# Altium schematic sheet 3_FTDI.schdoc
size 307 x 218 mm; Symbol: Sheet-Symbol_A4; Device: Sheet-Symbol_A4; @Project Name: Hexapod; @Page Count: 5; @Update Date: 2024-12-17; @Create Date: 2024-10-16; @Schematic Name: Schematic1; @Page No: 3; @Page Name: FTDI; Company: EasyEDA.com; Version: V1.0; Page Size: A4; @Create Time: 17:26:46; @Update Time: 18:06:18; Title Block Position: 3; Width: 1170; Height: 825; Region Start: 1; X Region Count: 6; Y Region Count: 4; Blade Width: 10; @Board Name: Hexapod
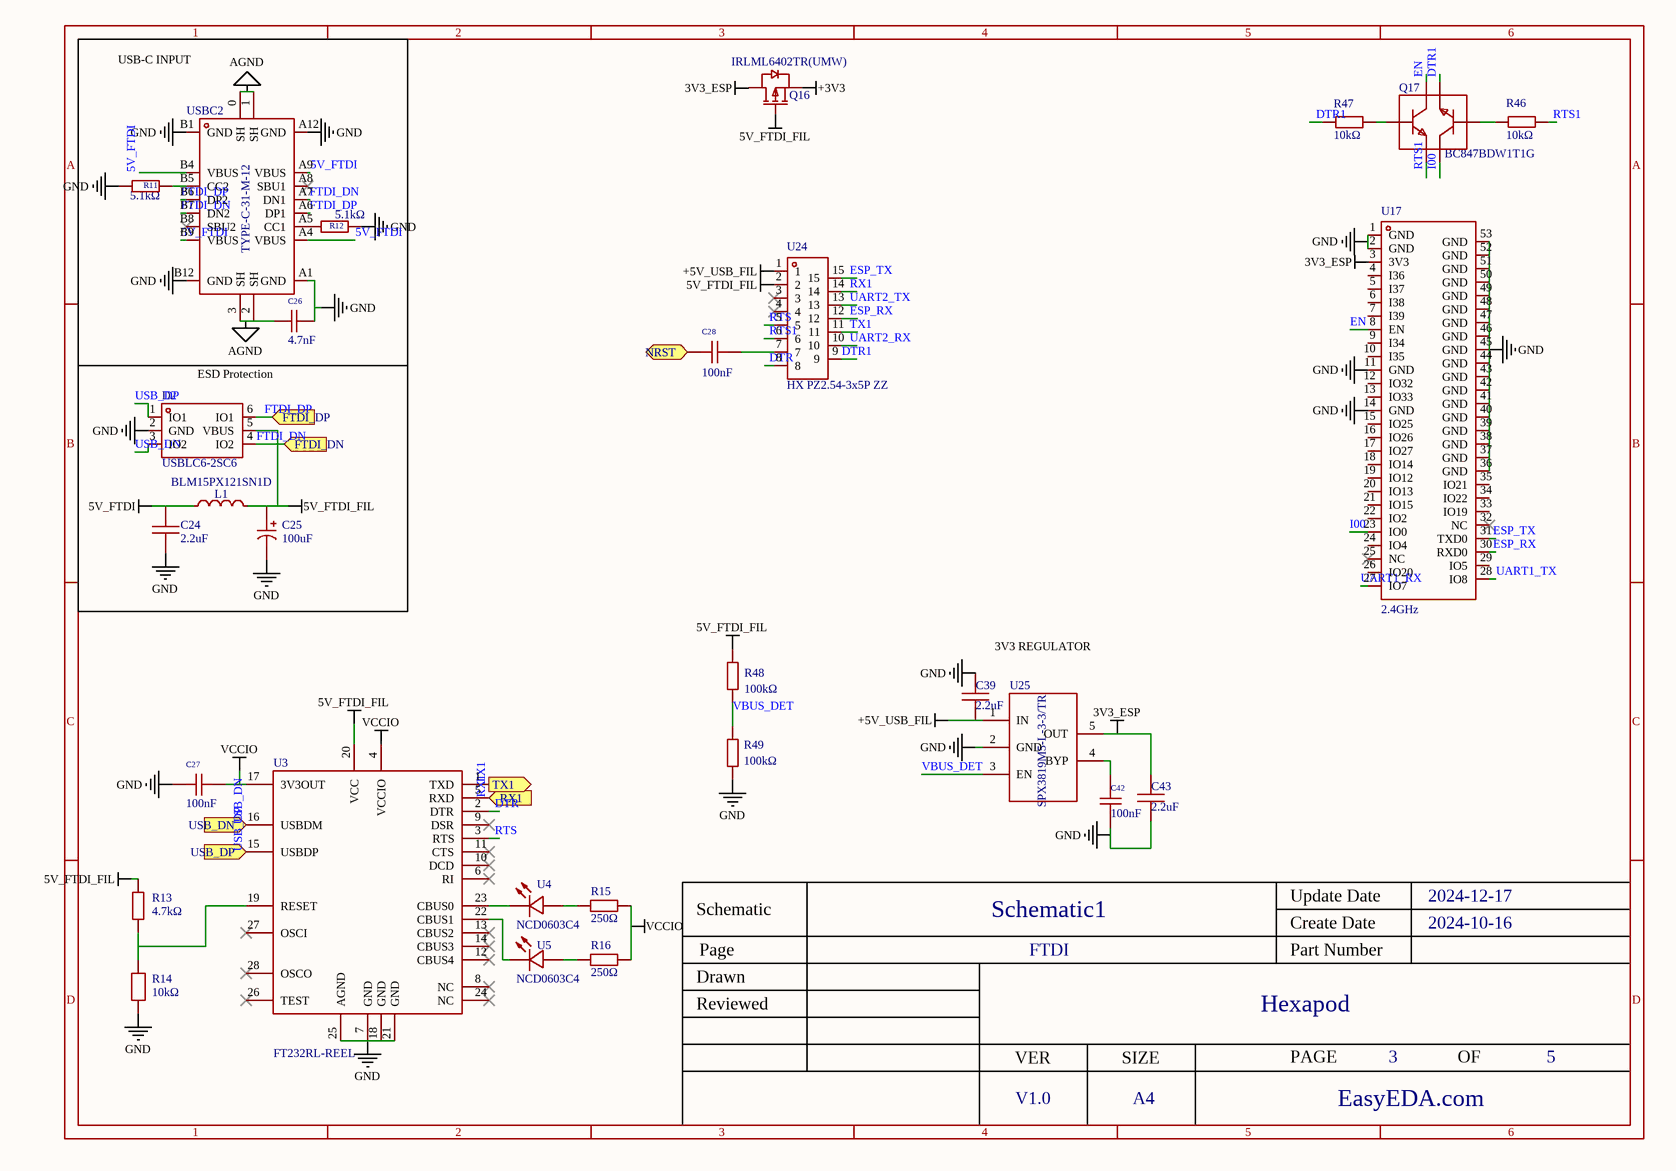
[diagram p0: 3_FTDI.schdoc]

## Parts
C24  2.2uF  [C0402]
C25  100uF  [CAP-SMD_BD5.0-L5.3-W5.3-LS6.3-FD]
C26  4.7nF  [C0402]
C27  100nF  [C0402]
C28  100nF  [C0603]
C39  2.2uF  [C0402]
C42  100nF  [C0402]
C43  2.2uF  [C0402]
D2  USBLC6-2SC6  [SOT-23-6_L2.9-W1.6-P0.95-LS2.8-BL]
L1  BLM15PX121SN1D  [L0402]
Q16  IRLML6402TR(UMW)  [SOT-23_L2.9-W1.3-P1.90-LS2.4-BR]
Q17  BC847BDW1T1G  [SOT-363_L2.0-W1.3-P0.65-LS2.1-TL]
R11  5.1kΩ  [R0402]
R12  5.1kΩ  [R0402]
R13  4.7kΩ  [R0603]
R14  10kΩ  [R0603]
R15  250Ω  [R0603]
R16  250Ω  [R0603]
R46  10kΩ  [R0402]
R47  10kΩ  [R0402]
R48  100kΩ  [R0402]
R49  100kΩ  [R0402]
U3  FT232RL-REEL  [SSOP-28_L10.2-W5.3-P0.65-LS7.8-BL]
U4  NCD0603C4  [LED0603-RD]
U5  NCD0603C4  [LED0603-RD]
U17  2.4GHz  [BULETM-SMD_ESP32-PICO-MINI-02-N8R2]
U24  HX PZ2.54-3x5P ZZ  [HDR-TH_15P-P2.54-V-M-R3-C5-S7.5]
U25  SPX3819M5-L-3-3/TR  [SOT-23-5_L3.0-W1.7-P0.95-LS2.8-BL]
USBC2  TYPE-C-31-M-12  [USB-C_SMD-TYPE-C-31-M-12]

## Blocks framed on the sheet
USB-C INPUT: C26 R11 R12 USBC2
ESD Protection: C24 C25 D2 L1

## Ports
FTDI_DN (in), FTDI_DP (in), NRST (bidir), RX1 (in), TX1 (out), USB_DN (in), USB_DP (in)

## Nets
3V3_ESP: C43.2 Q16.3(C) U17.3(3V3) U25.5(OUT)
5V_FTDI: C24.2 L1.1 USBC2.A4(VBUS) USBC2.A9(VBUS) USBC2.B4(VBUS) USBC2.B9(VBUS)
5V_FTDI_FIL: C25.1 D2.5(VBUS) L1.2 Q16.1(B) R13.2 R48.2 U3.20(VCC) U24.2
+3V3: Q16.2(E)
+5V_USB_FIL: C39.1 U24.1 U25.1(IN)
AGND: C26.1 USBC2.0(SH) USBC2.1(SH) USBC2.2(SH) USBC2.3(SH)
GND: C24.1 C25.2 C26.2 C27.1 C39.2 C42.1 C43.1 D2.2(GND) R11.1 R12.2 R14.2 R49.1 U3.7(GND) U3.18(GND) U3.21(GND) U3.25(AGND) U17.1(GND) U17.2(GND) U17.11(GND) U17.14(GND) U17.36(GND) U17.37(GND) U17.38(GND) U17.39(GND) U17.40(GND) U17.41(GND) U17.42(GND) U17.43(GND) U17.44(GND) U17.45(GND) U17.46(GND) U17.47(GND) U17.48(GND) U17.49(GND) U17.50(GND) U17.51(GND) U17.52(GND) U17.53(GND) U25.2(GND) USBC2.A1(GND) USBC2.A12(GND) USBC2.B1(GND) USBC2.B12(GND)
VCCIO: C27.2 R15.2 R16.2 U3.4(VCCIO) U3.17(3V3OUT)
DTR: U3.2(DTR) U24.8
DTR1: Q17.1(E) R47.1 U24.9
EN: Q17.3(C) U17.8(EN)
ESP_RX: U17.30(RXD0) U24.12
ESP_TX: U17.31(TXD0) U24.15
FTDI_DN: D2.4(IO2) USBC2.A7(DN1) USBC2.B7(DN2) ; port FTDI_DN
FTDI_DP: D2.6(IO1) USBC2.A6(DP1) USBC2.B6(DP2) ; port FTDI_DP
I00: Q17.6(C) U17.23(IO0)
NRST: C28.2 ; port NRST
RTS: U3.3(RTS) U24.5
RTS1: Q17.4(E) R46.2 U24.6
RX1: U3.5(RXD) U24.14 ; port RX1
TX1: U3.1(TXD) U24.11 ; port TX1
UART1_RX: U17.27(IO7)
UART1_TX: U17.28(IO8)
UART2_RX: U24.10
UART2_TX: U24.13
USB_DN: D2.3(IO2) U3.16(USBDM) ; port USB_DN
USB_DP: D2.1(IO1) U3.15(USBDP) ; port USB_DP
VBUS_DET: R48.1 R49.2 U25.3(EN)
NetC28_1: C28.1 U24.7
NetC42_2: C42.2 U25.4(BYP)
NetQ17_2: Q17.2(B) R46.1
NetQ17_5: Q17.5(B) R47.2
NetR11_2: R11.2 USBC2.B5(CC2)
NetR12_1: R12.1 USBC2.A5(CC1)
NetR13_1: R13.1 R14.1 U3.19(RESET)
NetR15_1: R15.1 U4.2(+)
NetR16_1: R16.1 U5.2(+)
NetU3_22: U3.22(CBUS1) U5.1(-)
NetU3_23: U3.23(CBUS0) U4.1(-)

Not connected (* = marked no-connect by the designer): U3 6(RI)* 8(NC)* 9(DSR)* 10(DCD)* 11(CTS)* 12(CBUS4)* 13(CBUS2)* 14(CBUS3)* 24(NC)* 26(TEST)* 27(OSCI)* 28(OSCO)*; U17 4(I36) 5(I37) 6(I38) 7(I39) 9(I34) 10(I35) 12(IO32) 13(IO33) 15(IO25) 16(IO26) 17(IO27) 18(IO14) 19(IO12) 20(IO13) 21(IO15) 22(IO2) 24(IO4) 25(NC)* 26(IO20) 29(IO5) 32(NC)* 33(IO19) 34(IO22) 35(IO21); U24 3* 4*; USBC2 A8(SBU1)* B8(SBU2)*

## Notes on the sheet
- 3V3 REGULATOR

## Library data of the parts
C24 C39 C43 = CL05A225MQ5NSNC: Manufacturer: SAMSUNG(三星); Add into BOM: yes; Tolerance: ±20%
C25 = RVT1C101M0505: Manufacturer: ROQANG(容强); Add into BOM: yes; Tolerance: ±20%; Ripple Current: 50mA@120Hz; Lifetime @ Temp: 2000hrs@105℃
C26 = CC0402KRX7R9BB472: Manufacturer: YAGEO(国巨); Add into BOM: yes; Tolerance: ±10%
C27 C42 = CC0402KRX7R7BB104: Manufacturer: YAGEO(国巨); Add into BOM: yes; Tolerance: ±10%
C28 = CC0603KRX7R9BB104: Manufacturer: YAGEO(国巨); Add into BOM: yes; Tolerance: ±10%
D2 = USBLC6-2SC6_C2827654: Manufacturer: TECH PUBLIC(台舟); Add into BOM: yes; polarity: Unidirectional; Reverse Stand-Off Voltage (Vrwm): 5V; Maximum Clamping Voltage: 12V; Peak Pulse Current (Ipp): 6A; Peak Pulse Power Dissipation (Ppp): 150W; Breakdown Voltage: 6V; Reverse Leakage Current (Ir): 80nA; Number of Lines: Dual channel; level of protection: IEC 61000-4-2; Type: ESD
L1 = BLM15PX121SN1D: Manufacturer: muRata(村田); Add into BOM: yes; Impedance @ Frequency: 120Ω@100MHz; Tolerance: ±25%; DC Resistance: 55mΩ; Current Rating: 2A; Circuits: 1
Q16 = IRLML6402TR(UMW): Manufacturer: UMW(友台半导体); Add into BOM: yes; Type: 1 Piece P-Channel; Drain Source On Resistance (RDS(on)@Vgs,Id): 65mΩ@4.5V,3.7A; Gate Threshold Voltage (Vgs(th)@Id): 950mV@250uA; Total Gate Charge (Qg@Vgs): 12nC@5V; Input Capacitance (Ciss@Vds): 633pF@10V
Q17 = BC847BDW1T1G: Manufacturer: onsemi(安森美); Add into BOM: yes; DC Current Gain (hFE@Ic,Vce): 150@10uA,5.0V; Transition Frequency (fT): 100MHz; Collector Cut-Off Current (Icbo): 5uA; Collector-Emitter Saturation Voltage (VCE(sat)@Ic,Ib): 0.25V@10mA,0.5mA
R11 R12 = RMC04025.1K1%N: Manufacturer: Tyohm(幸亚电阻); Add into BOM: yes; Tolerance: ±1%
R13 = RC0603JR-074K7L: Manufacturer: YAGEO(国巨); Add into BOM: yes; Tolerance: ±5%; Temperature Coefficient: ±100ppm/℃
R14 = FRC0603J103TS: Manufacturer: FOJAN(富捷); Add into BOM: yes; Tolerance: ±5%; Temperature Coefficient: ±100ppm/℃
R15 R16 = RT0603BRE07250RL: Manufacturer: YAGEO(国巨); Add into BOM: yes; Tolerance: ±0.1%; Temperature Coefficient: ±50ppm/℃
R46 R47 = RC0402FR-0710KL: Manufacturer: YAGEO(国巨); Add into BOM: yes; Tolerance: ±1%; Temperature Coefficient: ±100ppm/℃
R48 R49 = RC0402FR-07100KL: Manufacturer: YAGEO(国巨); Add into BOM: yes; Tolerance: ±1%; Temperature Coefficient: ±100ppm/℃
U3 = FT232RL-REEL: Manufacturer: FTDI(飞特帝亚); Add into BOM: yes; Applications Function: USB转UART; Protocol: UART; Supply Voltage: 3.3V~5.25V
U4 U5 = NCD0603C4: Manufacturer: 国星光电; Add into BOM: yes; Emitted Color: Green-yellow; Forward Voltage (VF): 1.6V~2.6V; Power Dissipation: 65mW; Forward Current: 25mA; Dominant Wavelength: 565nm~578nm; Peak Wavelength: 576nm; Lens Color: 无色透明透镜; Luminous Intensity: 5mcd~13mcd; Viewing Angle: 140°
U17 = ESP32-PICO-MINI-02-N8R2: Manufacturer: ESPRESSIF(乐鑫); Add into BOM: yes; Core Processor: ESP32 chip; Support Interface: I2C；SPI；UART；I2S; Output Power: 19.5dBm
U24 = HX PZ2.54-3x5P ZZ: Manufacturer: hanxia(韩下); Add into BOM: yes; Pin Structure: 3x5P; Pitch: 2.54mm; Circluar Pins/Square Pins: Policy; Current Rating (Max): 3A
U25 = SPX3819M5-L-3-3/TR: Manufacturer: MaxLinear(迈凌); Add into BOM: yes; Output Type: Fixed; Maximum Input Voltage: 16V; Output Voltage: 3.3V; Output Current: 500mA; Power Supply Rejection Ratio (PSRR): 70dB; Dropout Voltage: 700mV@(500mA); standby current: 8uA; Output Polarity: Positive electrode; Number of Outputs: 1
USBC2 = TYPE-C-31-M-12: Manufacturer: 韩国韩荣; Add into BOM: yes; Connector Type: Type-C; Gender: Female; Number of Contacts: 16P; Number of Ports: 1; Current Rating - Power (Max): 5A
